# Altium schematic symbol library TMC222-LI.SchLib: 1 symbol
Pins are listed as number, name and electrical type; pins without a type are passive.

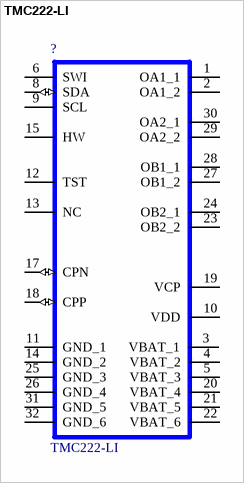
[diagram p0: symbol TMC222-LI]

## TMC222-LI
designator ?
Micro Stepping Stepper Motor Controller / Driver with Two Wire Serial Interface, QFN32(7x7); Manufacturer: TRINAMIC; Geometry.Height: 0,9mm; Ordercode - Distri#1: 1460-1051-ND
footprint TMC_QFN32_0.65_7.0X7.0
pins: 1 OA1_1, 2 OA1_2, 3 VBAT_1 (power), 4 VBAT_2 (power), 5 VBAT_3 (power), 6 SWI, 8 SDA (io), 9 SCL, 10 VDD (power), 11 GND_1, 12 TST, 13 NC, 14 GND_2, 15 HW, 17 CPN (io), 18 CPP (io), 19 VCP (power), 20 VBAT_4 (power), 21 VBAT_5 (power), 22 VBAT_6 (power), 23 OB2_2, 24 OB2_1, 25 GND_3, 26 GND_4, 27 OB1_2, 28 OB1_1, 29 OA2_2, 30 OA2_1, 31 GND_5, 32 GND_6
